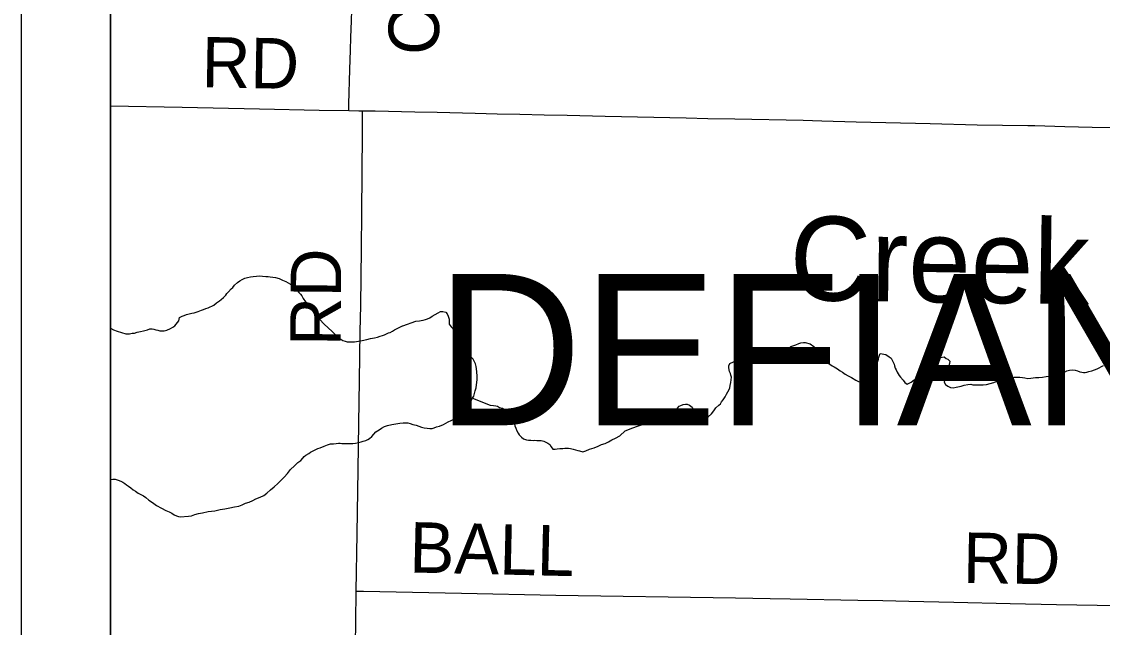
# Model space of a CAD drawing. Extents: x 0 to 34, y 0 to 22.
# Drawn here: x 23.417 to 24.635, y 15.894 to 16.577 of the extents above; entities that cross this region are included whole.
import ezdxf

# ---------------------------------------------------------------- set-up
doc = ezdxf.new("R2010")
doc.units = 0
for name, color, linetype in [('GM_X_County_Road', 7, 'Continuous'), ('GM_X_County_Road_Text', 7, 'Continuous'), ('GM_X_Minor_River', 7, 'Continuous'), ('GM_X_Minor_River_Text', 7, 'Continuous'), ('GM_X_Township_Road', 7, 'Continuous'), ('GM_X_Township_Road_Text', 7, 'Continuous'), ('GM_X_Township_Text', 7, 'Continuous'), ('SH_Data', 7, 'Continuous')]:
    doc.layers.add(name, color=color, linetype=linetype)

msp = doc.modelspace()

# ---------------------------------------------------------------- linework, layer by layer
at = {"layer": 'GM_X_County_Road'}
for points in [[(23.7853, 16.4763), (23.7855, 16.4836), (23.7866, 16.5228), (23.7874, 16.5445), (23.7878, 16.5588), (23.7884, 16.5774), (23.7898, 16.6259), (23.7918, 16.6899), (23.7932, 16.7309), (23.7945, 16.7837), (23.7971, 16.8613), (23.7981, 16.9017), (23.7995, 16.9496), (23.7998, 16.9576), (23.8002, 16.9701), (23.8004, 16.9788)], [(23.5167, 16.4819), (23.5977, 16.4803), (23.6847, 16.4785), (23.7519, 16.477), (23.7853, 16.4763)], [(23.7853, 16.4763), (23.7966, 16.476), (23.8008, 16.476)], [(23.7937, 15.9351), (23.7947, 15.9994), (23.7959, 16.0721), (23.7966, 16.1237), (23.7973, 16.1722), (23.7982, 16.2275), (23.7988, 16.2567), (23.7997, 16.3207), (23.8002, 16.3611), (23.8008, 16.4511), (23.8008, 16.476)], [(23.8008, 16.476), (23.8153, 16.4759), (23.86, 16.475), (23.8849, 16.4744), (23.9278, 16.4733), (23.9526, 16.4728), (23.9781, 16.4723), (24.0055, 16.4717), (24.0316, 16.4712), (24.0745, 16.4702), (24.1658, 16.4683), (24.19, 16.4676), (24.2205, 16.4669), (24.2976, 16.4654), (24.3187, 16.4649), (24.3572, 16.4638), (24.4405, 16.4618), (24.4934, 16.4605), (24.5506, 16.4596), (24.5586, 16.4594), (24.5922, 16.4586), (24.6233, 16.4577), (24.6929, 16.4566)], [(23.7852, 15.4328), (23.7853, 15.4414), (23.7873, 15.5396), (23.7877, 15.5675), (23.788, 15.5949), (23.7886, 15.6322), (23.7895, 15.6918), (23.7907, 15.7415), (23.7913, 15.7657), (23.7918, 15.8055), (23.7928, 15.8726), (23.7937, 15.9329), (23.7937, 15.9351)]]:
    msp.add_lwpolyline(points, dxfattribs=at)
at = {"layer": 'GM_X_Minor_River'}
for points in [[(23.5939, 16.2395), (23.5946, 16.2434), (23.5977, 16.2449), (23.6, 16.2456), (23.6026, 16.2466), (23.6084, 16.248), (23.6111, 16.2487), (23.6133, 16.2494), (23.6156, 16.2501), (23.6195, 16.2515), (23.6218, 16.2522), (23.6241, 16.2533), (23.6268, 16.254), (23.6291, 16.2551), (23.631, 16.2562), (23.6333, 16.2572), (23.6364, 16.2598), (23.6395, 16.262), (23.6414, 16.2635), (23.6441, 16.2657), (23.6469, 16.2683), (23.6481, 16.2702), (23.65, 16.272), (23.6528, 16.2757), (23.6547, 16.2772), (23.6567, 16.2798), (23.6598, 16.2828), (23.6625, 16.2846), (23.6652, 16.2861), (23.6682, 16.2875), (23.6713, 16.2882), (23.6747, 16.2892), (23.6778, 16.2895), (23.6812, 16.2898), (23.6846, 16.2901), (23.6881, 16.29), (23.6918, 16.2895), (23.6945, 16.2895), (23.6968, 16.289), (23.6998, 16.2886), (23.7028, 16.2885), (23.707, 16.2873), (23.7107, 16.2853), (23.7145, 16.284), (23.7171, 16.2824), (23.7197, 16.2809), (23.722, 16.2793), (23.7249, 16.2762), (23.7272, 16.2738), (23.729, 16.2715), (23.7309, 16.2695), (23.7323, 16.2676), (23.7341, 16.2645), (23.7367, 16.261), (23.7389, 16.2583), (23.7408, 16.256), (23.7426, 16.2537), (23.7441, 16.2517), (23.7455, 16.2494), (23.7485, 16.2463), (23.7496, 16.2444), (23.7522, 16.2413), (23.7577, 16.2359)], [(23.8462, 16.234), (23.8611, 16.2392), (23.8649, 16.2395), (23.8669, 16.2398), (23.8691, 16.2402), (23.8718, 16.2409), (23.8741, 16.2419), (23.8768, 16.243), (23.8795, 16.2448), (23.8826, 16.2467), (23.8861, 16.2485), (23.8888, 16.2499), (23.8914, 16.2502), (23.8948, 16.2494), (23.8963, 16.2474), (23.8974, 16.2448), (23.8984, 16.2413), (23.8987, 16.2356), (23.9008, 16.2328)], [(23.5167, 16.2312), (23.5203, 16.2292), (23.5244, 16.2279), (23.5293, 16.2262), (23.5342, 16.2249), (23.5381, 16.2248), (23.5411, 16.2255), (23.5438, 16.2257), (23.5469, 16.2268), (23.5507, 16.2274), (23.5542, 16.2284), (23.5584, 16.2294), (23.5611, 16.2305), (23.5637, 16.2304), (23.5656, 16.23), (23.5679, 16.2295), (23.5702, 16.2291), (23.5724, 16.2282), (23.5743, 16.2281), (23.5774, 16.2284), (23.5805, 16.2291), (23.5843, 16.2309), (23.587, 16.2323), (23.5894, 16.2337), (23.5939, 16.2395)], [(23.7577, 16.2359), (23.7666, 16.2274), (23.7685, 16.2255), (23.7714, 16.2223), (23.7744, 16.2199), (23.7763, 16.2187), (23.7785, 16.2175), (23.7812, 16.2167), (23.7834, 16.2158), (23.7861, 16.2157), (23.7884, 16.2157), (23.7918, 16.2159), (23.7964, 16.2165), (23.8006, 16.2175), (23.8056, 16.2185), (23.8098, 16.2195), (23.8144, 16.2205), (23.8179, 16.2212), (23.8206, 16.2222), (23.8232, 16.2229), (23.8256, 16.2239), (23.8279, 16.225), (23.8302, 16.2261), (23.8321, 16.2264), (23.8348, 16.2278), (23.8368, 16.2293), (23.8461, 16.234)], [(23.9009, 16.1274), (23.9037, 16.1289), (23.9056, 16.13), (23.9072, 16.1318), (23.9092, 16.1344), (23.9119, 16.1377), (23.9151, 16.141), (23.9182, 16.1444), (23.9214, 16.1477), (23.9238, 16.1503), (23.925, 16.1525), (23.9262, 16.1548), (23.927, 16.1578), (23.9279, 16.1608), (23.9288, 16.1642), (23.9302, 16.1733), (23.9299, 16.1771), (23.9297, 16.182), (23.9295, 16.1855), (23.9288, 16.1881), (23.9281, 16.1912), (23.927, 16.1935), (23.9256, 16.1962), (23.9234, 16.1986), (23.9216, 16.2013), (23.9186, 16.2048), (23.9161, 16.208), (23.9139, 16.2107), (23.9124, 16.2127), (23.9113, 16.2146), (23.9103, 16.2165), (23.9096, 16.2185), (23.9085, 16.2208), (23.9074, 16.2231), (23.9064, 16.2258), (23.9053, 16.2277), (23.9031, 16.2305), (23.9008, 16.2328)], [(24.2075, 16.1507), (24.2095, 16.154), (24.2111, 16.157), (24.2124, 16.1597), (24.214, 16.1623), (24.2148, 16.1641), (24.2153, 16.1668), (24.2161, 16.1702), (24.2167, 16.1759), (24.216, 16.1782), (24.2157, 16.1801), (24.2146, 16.1824), (24.2139, 16.1843), (24.2136, 16.187), (24.2137, 16.1889), (24.2149, 16.1915), (24.2188, 16.1933), (24.2211, 16.1932), (24.2252, 16.1927), (24.2271, 16.1927), (24.229, 16.1926), (24.2321, 16.1929), (24.2344, 16.1928), (24.2374, 16.1931), (24.2405, 16.193), (24.2443, 16.1932), (24.2489, 16.1942), (24.252, 16.1949), (24.2547, 16.1959), (24.2585, 16.1977), (24.2631, 16.1994), (24.2678, 16.2016), (24.2716, 16.203), (24.2743, 16.2044), (24.2763, 16.2059), (24.2798, 16.2073), (24.2837, 16.2106), (24.2891, 16.2123), (24.2926, 16.2141), (24.2949, 16.2148), (24.2979, 16.215), (24.2998, 16.215), (24.3055, 16.2136), (24.3096, 16.2105), (24.3114, 16.2089), (24.3133, 16.2073), (24.3151, 16.2053), (24.318, 16.201), (24.3202, 16.1979), (24.3224, 16.1952), (24.3243, 16.1932), (24.3265, 16.1913), (24.3302, 16.1888), (24.3325, 16.1876), (24.3343, 16.1864), (24.3362, 16.1856), (24.3392, 16.1832), (24.3418, 16.1816), (24.3448, 16.1796), (24.3481, 16.1776), (24.3519, 16.1756), (24.3567, 16.1727), (24.3597, 16.1711), (24.362, 16.1703), (24.3643, 16.1698), (24.3662, 16.1701), (24.37, 16.1715), (24.3736, 16.1745), (24.3755, 16.1767), (24.3767, 16.1785), (24.3776, 16.1816), (24.3784, 16.1842), (24.3793, 16.1865), (24.3801, 16.1895), (24.381, 16.1917), (24.3818, 16.194), (24.3822, 16.1962), (24.3827, 16.1985), (24.3835, 16.2008), (24.3844, 16.2026), (24.3908, 16.2017), (24.3945, 16.1989), (24.3968, 16.1973), (24.3985, 16.1938), (24.4, 16.1907), (24.4003, 16.1888), (24.4013, 16.1861), (24.4024, 16.1842), (24.4035, 16.1818), (24.4046, 16.1799), (24.4057, 16.178), (24.4071, 16.176), (24.4101, 16.1725), (24.4119, 16.1701), (24.4145, 16.1682), (24.4168, 16.1692), (24.4191, 16.1703), (24.4226, 16.1732), (24.4253, 16.1743), (24.4285, 16.1772), (24.4301, 16.1794)], [(24.4301, 16.1794), (24.4317, 16.1817), (24.4333, 16.1847), (24.4349, 16.1869), (24.4376, 16.1898), (24.4396, 16.1921), (24.4424, 16.1942), (24.4447, 16.1953), (24.4485, 16.1967), (24.4524, 16.1981), (24.4562, 16.1991), (24.4588, 16.1971), (24.4607, 16.1963), (24.4629, 16.1939), (24.4624, 16.1913), (24.4616, 16.189), (24.4608, 16.1868), (24.46, 16.1849), (24.4591, 16.1823), (24.4586, 16.1796), (24.4578, 16.1774), (24.457, 16.1744), (24.4565, 16.1706), (24.4579, 16.1679), (24.4605, 16.1659), (24.4635, 16.1646), (24.4665, 16.1641), (24.47, 16.1648), (24.4757, 16.1661), (24.4788, 16.1672), (24.483, 16.1678), (24.4865, 16.1681), (24.4887, 16.1676), (24.491, 16.1675), (24.4941, 16.1674), (24.4971, 16.1673), (24.5005, 16.1676), (24.504, 16.1679), (24.5082, 16.1689), (24.5124, 16.1702), (24.5167, 16.172), (24.522, 16.173), (24.5255, 16.1736), (24.5282, 16.1743), (24.5313, 16.1753), (24.5351, 16.176), (24.5385, 16.1762), (24.5416, 16.1761), (24.5446, 16.1756), (24.5472, 16.1752), (24.5507, 16.1747), (24.5541, 16.1749), (24.5594, 16.1755), (24.5629, 16.1758), (24.5671, 16.176), (24.5713, 16.1767), (24.5755, 16.1773), (24.5789, 16.1775), (24.582, 16.1782), (24.5854, 16.1788), (24.5889, 16.1799), (24.592, 16.1817), (24.5947, 16.1831), (24.5978, 16.1841), (24.6012, 16.1844), (24.6039, 16.1839), (24.6065, 16.1831), (24.6092, 16.1822), (24.6114, 16.1818), (24.6133, 16.1814), (24.6152, 16.1813), (24.6171, 16.1816), (24.6195, 16.1823), (24.6229, 16.1833), (24.626, 16.1844), (24.6287, 16.1854), (24.6361, 16.1893)], [(23.925, 16.1525), (23.9449, 16.1446), (23.9483, 16.1441), (23.951, 16.1437), (23.9529, 16.1432), (23.9551, 16.142), (23.9585, 16.1411), (23.9619, 16.1387), (23.9641, 16.1367), (23.9652, 16.1348), (23.9666, 16.1329), (23.9688, 16.1301), (23.9706, 16.1274), (23.9717, 16.1251), (23.9727, 16.1212), (23.9738, 16.1185), (23.9748, 16.1155), (23.9763, 16.1131), (23.9774, 16.1112), (23.9799, 16.1084), (23.9822, 16.1065), (23.9856, 16.1056), (23.9878, 16.1051), (23.9905, 16.105), (23.9931, 16.1046), (23.9951, 16.1049), (23.9973, 16.1048), (23.9996, 16.1047), (24.0023, 16.1047), (24.0053, 16.1038), (24.0076, 16.103), (24.0098, 16.1017), (24.012, 16.1001), (24.0135, 16.0974), (24.0153, 16.0951), (24.018, 16.095), (24.0203, 16.0953), (24.0233, 16.0956), (24.0268, 16.0958), (24.0287, 16.0962), (24.0306, 16.0961), (24.0329, 16.096), (24.0351, 16.0956), (24.0382, 16.0951), (24.0408, 16.0942), (24.0434, 16.0934), (24.0453, 16.0929), (24.0491, 16.0921), (24.0526, 16.0931), (24.0568, 16.0948), (24.0618, 16.0966), (24.0664, 16.0983), (24.0703, 16.1001), (24.0742, 16.1015), (24.078, 16.1033), (24.0819, 16.1054), (24.0861, 16.1072), (24.0908, 16.1101), (24.0967, 16.1156), (24.1056, 16.1191), (24.1106, 16.1208), (24.114, 16.1218), (24.1167, 16.1229), (24.1198, 16.1243), (24.1229, 16.1265), (24.1272, 16.129), (24.1307, 16.1308), (24.1338, 16.1326), (24.1361, 16.1337), (24.1396, 16.1347), (24.1419, 16.1346), (24.1449, 16.1349), (24.1476, 16.1352), (24.1495, 16.1359), (24.1519, 16.1373), (24.1558, 16.141), (24.1578, 16.1432), (24.1597, 16.1443), (24.1624, 16.1453), (24.1647, 16.1457), (24.1666, 16.1456), (24.1692, 16.1444), (24.1722, 16.1424), (24.174, 16.1385), (24.1739, 16.1347), (24.173, 16.1317), (24.1733, 16.129), (24.1752, 16.1278), (24.1771, 16.1274), (24.1793, 16.1269), (24.1816, 16.1276), (24.1847, 16.1286), (24.1874, 16.1293), (24.1905, 16.1315), (24.1941, 16.1348), (24.1968, 16.1381), (24.1992, 16.1415), (24.2024, 16.1444), (24.2043, 16.1462), (24.2055, 16.1481), (24.2075, 16.1507)], [(23.545, 16.0476), (23.5479, 16.0453), (23.5517, 16.0436), (23.5539, 16.0424), (23.5565, 16.0404), (23.5599, 16.0376), (23.564, 16.0348), (23.5688, 16.0313), (23.5744, 16.0284), (23.5793, 16.026), (23.5831, 16.0243), (23.5861, 16.0227), (23.5887, 16.0211), (23.5913, 16.0198), (23.5936, 16.019), (23.5954, 16.0186), (23.6046, 16.0194), (23.6081, 16.02), (23.6119, 16.0214), (23.6161, 16.0224), (23.6207, 16.0234), (23.6269, 16.0247), (23.6345, 16.0256), (23.6403, 16.027), (23.6456, 16.0279), (23.6514, 16.0289), (23.6567, 16.0298), (23.6613, 16.0308), (23.6652, 16.0322), (23.6691, 16.034), (23.6733, 16.0354), (23.6772, 16.0371), (23.6806, 16.0389), (23.6857, 16.041), (23.6895, 16.0428), (23.693, 16.0454), (23.697, 16.049), (23.7013, 16.0527), (23.7056, 16.0564), (23.7091, 16.06), (23.7127, 16.0634), (23.7162, 16.0674), (23.7198, 16.0719), (23.7241, 16.0763), (23.728, 16.08), (23.7315, 16.0821), (23.7335, 16.0847), (23.7351, 16.0866), (23.7371, 16.088), (23.7402, 16.0902), (23.7421, 16.0917), (23.7444, 16.0927), (23.7475, 16.0941), (23.7506, 16.0956), (23.7533, 16.0966), (23.7576, 16.0984), (23.7614, 16.0998), (23.7649, 16.1008), (23.7683, 16.1011), (23.771, 16.1013), (23.7737, 16.1016), (23.7756, 16.1016), (23.7775, 16.1015), (23.7794, 16.1014), (23.782, 16.1014), (23.79, 16.1015), (23.7931, 16.1018), (23.7965, 16.1024), (23.7992, 16.1031), (23.8015, 16.1038), (23.8046, 16.1048), (23.8069, 16.1059), (23.8089, 16.1069), (23.8112, 16.1091), (23.8136, 16.1117), (23.816, 16.1143), (23.8195, 16.1169), (23.8222, 16.1187), (23.8257, 16.1204), (23.8291, 16.1215), (23.8338, 16.1228), (23.8384, 16.1234), (23.8429, 16.1241), (23.8468, 16.1247), (23.8494, 16.1246), (23.8521, 16.1245), (23.8547, 16.124), (23.8574, 16.1228), (23.8612, 16.1219), (23.8642, 16.1207), (23.8672, 16.1198), (23.8702, 16.119), (23.8736, 16.1185), (23.8767, 16.1184), (23.8793, 16.1183), (23.8816, 16.119), (23.8843, 16.12), (23.8878, 16.121), (23.892, 16.1228), (23.8975, 16.1257), (23.9009, 16.1274)], [(23.5167, 16.0608), (23.5195, 16.0611), (23.5222, 16.061), (23.5256, 16.0601), (23.5286, 16.0588), (23.5308, 16.0576), (23.5331, 16.0564), (23.5349, 16.0548), (23.5371, 16.0532), (23.5397, 16.0512), (23.5424, 16.0493), (23.545, 16.0476)]]:
    msp.add_lwpolyline(points, dxfattribs=at)
at = {"layer": 'GM_X_Township_Road'}
for points in [[(24.7215, 18.313), (24.6064, 18.5004), (24.5339, 18.5567), (24.4603, 18.5785), (24.3637, 18.583), (24.2856, 18.5622), (24.1994, 18.53), (24.12, 18.538), (24.0257, 18.5782), (23.9624, 18.631), (23.898, 18.7), (23.8186, 18.7551), (23.7407, 18.7883), (23.6866, 18.7918), (23.6395, 18.7618), (23.6269, 18.7216), (23.6328, 18.5687), (23.627, 18.5353), (23.5995, 18.4744), (23.5512, 18.4226), (23.5167, 18.4074), (23.5167, 14.1)], [(23.7937, 15.9351), (23.8018, 15.9349), (23.9124, 15.9329), (24.0187, 15.9304), (24.2212, 15.9275), (24.2604, 15.9268), (24.2828, 15.9264), (24.3592, 15.9248), (24.3872, 15.9243), (24.4164, 15.9238), (24.4673, 15.9225), (24.5307, 15.9209), (24.5829, 15.92), (24.6519, 15.919)]]:
    msp.add_lwpolyline(points, dxfattribs=at)
at = {"layer": 'SH_Data'}
for points in [[(23.4167, 21), (30.4167, 21), (30.4167, 14), (23.4167, 14)], [(23.5167, 20.9), (30.3167, 20.9), (30.3167, 14.1), (23.5167, 14.1)]]:
    msp.add_lwpolyline(points, close=True, dxfattribs=at)

# ---------------------------------------------------------------- texts
at = {"layer": 'GM_X_County_Road_Text'}
for s, rotation, p in [('C-146', 88.3635, (23.8863, 16.5383)), ('RD', 359.0174, (23.6192, 16.5026)), ('RD', 89.5067, (23.7761, 16.211))]:
    msp.add_text(s, height=0.05682, rotation=rotation, dxfattribs=at).set_placement(p)
at = {"layer": 'GM_X_Minor_River_Text'}
msp.add_text('Creek', height=0.09474, rotation=359.1767, dxfattribs=at).set_placement((24.2817, 16.2629))
at = {"layer": 'GM_X_Township_Road_Text'}
for s, rotation, p in [('BALL', 358.6882, (23.8532, 15.9561)), ('RD', 359.0128, (24.4772, 15.9444))]:
    msp.add_text(s, height=0.05682, rotation=rotation, dxfattribs=at).set_placement(p)
at = {"layer": 'GM_X_Township_Text'}
msp.add_text('DEFIANCE', height=0.17045, rotation=0, dxfattribs=at).set_placement((23.8838, 16.1219))

doc.saveas('drawing.dxf')
